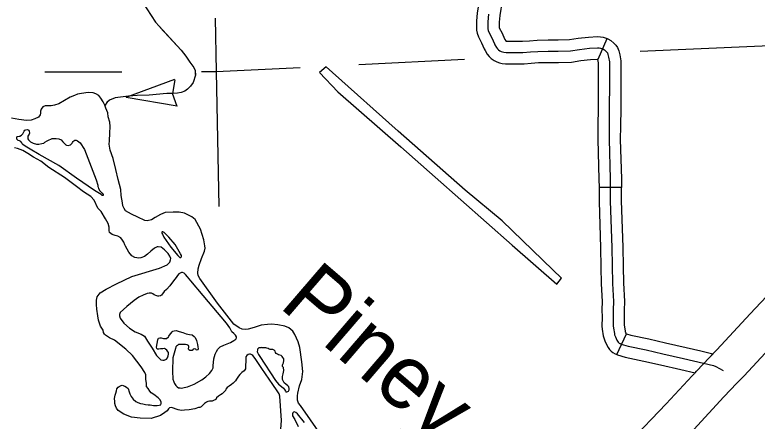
# Model space of a CAD drawing. Extents: x 1084508 to 1142749, y 1057638 to 1093403.
# Drawn here: x 1112809 to 1114355, y 1060030 to 1060877 of the extents above; entities that cross this region are included whole.
import ezdxf

# ---------------------------------------------------------------- set-up
doc = ezdxf.new("R2010")
doc.units = 0
for name, color, linetype in [('Level 15', 7, 'Continuous'), ('Level 31', 7, 'Continuous'), ('Level 35', 7, 'Continuous'), ('Level 43', 7, 'Continuous'), ('Level 45', 7, 'Continuous'), ('Level 5', 7, 'Continuous'), ('Level 57', 7, 'Continuous')]:
    doc.layers.add(name, color=color, linetype=linetype)

msp = doc.modelspace()

# ---------------------------------------------------------------- linework, layer by layer
at = {"layer": 'Level 15'}
for points in [[(1114859, 1060806.8), (1114846.4, 1060793), (1114811.6, 1060755.8), (1114767.8, 1060709.4), (1114736.5, 1060676.9), (1114672.2, 1060608), (1114640.1, 1060572.8), (1114610, 1060541.7), (1114560.6, 1060488.9), (1114524.7, 1060450.4), (1114468.5, 1060391.1), (1114419.6, 1060338.5), (1114340.5, 1060254), (1114270.6, 1060179), (1114255.7, 1060163.4)], [(1114312.6, 1060109.4), (1114327.7, 1060125.1), (1114397.9, 1060200.5), (1114477, 1060285), (1114525.8, 1060337.5), (1114581.8, 1060396.7), (1114617.9, 1060435.3), (1114666.9, 1060487.6), (1114697.3, 1060519.1), (1114729.8, 1060554.8), (1114793.4, 1060622.8), (1114824.6, 1060655.2), (1114868.9, 1060702.1), (1114904, 1060739.7), (1114916.9, 1060753.8)], [(1114255.7, 1060163.4), (1114228.4, 1060134.4), (1114165.6, 1060066.6), (1114088.6, 1059985.7), (1114069.7, 1059965.9), (1114032.8, 1059925.7), (1113985.7, 1059876.6), (1113949.2, 1059837.5), (1113930.3, 1059817.1)], [(1113990.5, 1059766.6), (1114006.7, 1059784.2), (1114042.7, 1059822.7), (1114089.9, 1059872), (1114127, 1059912.3), (1114145.4, 1059931.6), (1114222.8, 1060012.9), (1114285.7, 1060080.8), (1114312.6, 1060109.4)]]:
    msp.add_lwpolyline(points, dxfattribs=at)
at = {"layer": 'Level 31'}
for p, q in [((1114072.5, 1060517.8), (1114025.5, 1060517.8)), ((1114062.8, 1060169.3), (1114082.5, 1060212.5))]:
    msp.add_line(p, q, dxfattribs=at)
for points in [[(1114025.5, 1060517.8), (1114025.5, 1060488.5), (1114028.8, 1060391.8), (1114029.5, 1060351.7)], [(1114049, 1060517.8), (1114049, 1060488.9), (1114052.3, 1060392.4), (1114053.7, 1060317.7), (1114055.8, 1060279.9), (1114055.3, 1060262.2), (1114055.3, 1060247.2), (1114055.3, 1060229.4), (1114055.6, 1060224.6), (1114057.5, 1060213.2), (1114058.1, 1060210.5), (1114059.5, 1060206.2), (1114062.6, 1060199.5), (1114064, 1060197), (1114065.6, 1060194.9), (1114066.4, 1060194.1), (1114067.8, 1060193), (1114069.5, 1060192), (1114071.5, 1060191.2), (1114085.9, 1060186.9), (1114123.7, 1060178.8), (1114158.5, 1060170.6), (1114201.4, 1060161.3), (1114243, 1060151.3), (1114263.6, 1060146.3), (1114268.7, 1060144.5), (1114276.6, 1060140.3), (1114284, 1060136.3)], [(1114076.6, 1060352.5), (1114075.9, 1060393), (1114072.6, 1060489.4), (1114072.5, 1060517.8)], [(1114029.5, 1060351.7), (1114030.1, 1060316.8), (1114032.3, 1060279.6), (1114031.7, 1060262.5), (1114031.8, 1060247.3), (1114031.7, 1060228.6), (1114032.2, 1060221.9), (1114034.4, 1060208.5), (1114035.4, 1060204.1), (1114037.5, 1060197.7), (1114041.7, 1060188.6), (1114044.3, 1060184.1), (1114047.5, 1060179.8), (1114050.6, 1060176.5), (1114054.5, 1060173.5), (1114059.2, 1060170.7), (1114062.8, 1060169.3)], [(1114082.5, 1060212.5), (1114081.5, 1060214.8), (1114080.8, 1060216.8), (1114080.6, 1060217.9), (1114079, 1060227.4), (1114078.8, 1060230.2), (1114078.8, 1060247.2), (1114078.8, 1060261.8), (1114079.4, 1060280.2), (1114077.2, 1060318.6), (1114076.6, 1060352.5)], [(1114082.5, 1060212.5), (1114091.8, 1060209.7), (1114128.9, 1060201.7), (1114163.7, 1060193.5), (1114206.7, 1060184.3), (1114237.8, 1060176.7)], [(1114237.8, 1060176.7), (1114248.5, 1060174.2), (1114262.7, 1060170.7)], [(1114062.8, 1060169.3), (1114064, 1060168.9), (1114080.1, 1060164), (1114118.6, 1060155.8), (1114153.3, 1060147.6), (1114196.2, 1060138.4), (1114225.5, 1060131.3)], [(1114225.5, 1060131.3), (1114228.4, 1060134.4), (1114255.7, 1060163.4), (1114262.7, 1060170.7)]]:
    msp.add_lwpolyline(points, dxfattribs=at)
at = {"layer": 'Level 35'}
for points in [[(1113205.1, 1060396.2), (1113202.6, 1060408.4), (1113195.7, 1060430.6), (1113185, 1060450.7), (1113177.8, 1060456.5), (1113162.4, 1060464), (1113151.3, 1060466.2), (1113138.7, 1060466.2), (1113122.2, 1060465.1), (1113112.5, 1060461.5), (1113101.4, 1060454.7), (1113093.5, 1060450.4), (1113084.9, 1060448.2), (1113080.2, 1060448.6), (1113065.5, 1060455.4), (1113052.2, 1060462.2), (1113040, 1060469), (1113036.8, 1060473.7), (1113034.3, 1060479.1), (1113033.2, 1060485.6), (1113031, 1060500.6), (1113030, 1060513.6), (1113024.6, 1060534), (1113019.6, 1060554.8), (1113014.2, 1060577.8), (1113008.1, 1060595.4), (1113005.9, 1060607.6), (1113006.3, 1060614.8), (1113007, 1060630.6), (1113008.1, 1060644.6), (1113007, 1060653.5), (1113003.8, 1060664.7), (1113002.7, 1060672.9), (1112999.1, 1060683), (1112996.6, 1060689.1), (1112993, 1060695.9), (1112988.7, 1060703.4), (1112984, 1060709.5), (1112977.9, 1060712.8), (1112972.6, 1060714.6), (1112961.8, 1060715.6), (1112948, 1060713.6), (1112939.5, 1060712.1), (1112933.8, 1060709.2), (1112924.5, 1060706), (1112913, 1060698.8), (1112900.8, 1060692), (1112891.6, 1060689), (1112885, 1060688), (1112877.8, 1060688)], [(1112877.8, 1060688), (1112872.8, 1060687.6), (1112867.8, 1060685.5), (1112863.8, 1060680.8), (1112863.1, 1060676.9), (1112863.1, 1060672.6), (1112862, 1060669), (1112858.8, 1060664), (1112850.9, 1060660.4), (1112843, 1060658.2), (1112833.7, 1060657.5), (1112817.9, 1060659.3), (1112802.5, 1060661.8)], [(1113134.1, 1060369.3), (1113131.8, 1060374.6), (1113128.4, 1060380), (1113120.7, 1060387.6), (1113117.3, 1060390.6), (1113113.9, 1060392.9), (1113107.8, 1060393.7), (1113105.9, 1060393.7), (1113099.8, 1060391), (1113092.5, 1060384.5), (1113085.3, 1060378.8), (1113079.2, 1060373.8), (1113071.9, 1060371.2), (1113067.7, 1060370), (1113059.3, 1060371.6), (1113052.9, 1060375.4), (1113046.4, 1060382.6), (1113039.5, 1060395.2), (1113038.4, 1060398.3), (1113036.1, 1060403.2), (1113033.8, 1060407.8), (1113030, 1060412.4), (1113023.5, 1060416.2), (1113018.5, 1060417.7), (1113012, 1060419.6), (1113009, 1060421.5), (1113006.3, 1060423.8), (1113005.9, 1060427.6), (1113005.9, 1060434.9), (1113003.7, 1060442.5), (1112997.9, 1060452.4), (1112989.2, 1060467.3), (1112982.3, 1060474.6), (1112974.3, 1060491), (1112967.4, 1060499), (1112952.2, 1060508.5), (1112937.7, 1060519.6), (1112912.5, 1060538.3), (1112880.1, 1060558.9), (1112863.3, 1060572.6), (1112848, 1060581), (1112836.2, 1060588.3), (1112825.9, 1060594.8), (1112814.9, 1060599), (1112808.4, 1060600.5)], [(1113458.4, 1059985.5), (1113425, 1060032.9), (1113403.9, 1060063.4), (1113399.9, 1060068.1), (1113397.8, 1060074.5), (1113397.8, 1060083.2), (1113398.5, 1060088.5), (1113402.1, 1060104.3), (1113407.1, 1060117.3), (1113409.2, 1060133.8), (1113407.1, 1060153.9), (1113402.8, 1060184), (1113399.5, 1060195.5), (1113392.4, 1060211.3), (1113388.1, 1060218.1), (1113379.8, 1060224.9), (1113371.6, 1060228.5), (1113357.2, 1060231.4), (1113343.6, 1060232.8), (1113335.3, 1060231.8), (1113322.4, 1060230.7), (1113307.3, 1060226), (1113295.1, 1060222.1), (1113289, 1060221.7), (1113282.9, 1060222.1), (1113276.1, 1060224.9), (1113265.4, 1060232.5), (1113231.3, 1060276.6), (1113194.7, 1060327.6), (1113190.7, 1060334.4), (1113190, 1060339.1), (1113191.1, 1060347.7), (1113192.9, 1060355.6), (1113197.9, 1060369.6), (1113204.4, 1060385), (1113205.4, 1060390.8), (1113205.1, 1060396.2)], [(1113055.5, 1060076.2), (1113060.9, 1060071.7), (1113065.4, 1060069), (1113071.2, 1060067.1), (1113075.7, 1060066.3), (1113081.5, 1060065.2), (1113087.2, 1060064.4), (1113091.4, 1060064.4), (1113094.4, 1060063.6), (1113098.2, 1060062.9), (1113101.7, 1060062.9), (1113105.5, 1060062.9), (1113109.7, 1060063.6), (1113113.1, 1060064.8), (1113113.9, 1060067.5), (1113114.3, 1060069.8), (1113112, 1060074.7), (1113107.4, 1060079.3), (1113099, 1060086.2), (1113093.3, 1060089.6), (1113090.6, 1060093), (1113086.8, 1060098.4), (1113083.7, 1060102.9), (1113083.7, 1060108.7), (1113081.8, 1060117.8), (1113081.8, 1060127), (1113080.3, 1060131.6), (1113072.3, 1060143.8), (1113054.4, 1060167), (1113040.7, 1060180.8), (1113016.6, 1060199.5), (1113006.7, 1060204.4), (1112998.3, 1060209.8), (1112996, 1060212.1), (1112994.1, 1060215.1), (1112993, 1060220.1), (1112988, 1060228.5), (1112983.4, 1060241.1), (1112981.9, 1060249.8), (1112980, 1060264), (1112979.2, 1060273.5), (1112979.2, 1060282.7), (1112980.8, 1060289.5), (1112987.3, 1060297.9), (1112999.5, 1060305.5), (1113020.8, 1060317), (1113053.2, 1060332.3), (1113110.4, 1060349.4), (1113126.8, 1060356.3), (1113132.2, 1060361.6), (1113133.7, 1060366.6), (1113134.1, 1060369.3)], [(1113250, 1060234.4), (1113201.2, 1060292.1), (1113175.4, 1060323), (1113168.6, 1060331.6), (1113164.7, 1060335.9), (1113161.8, 1060338.8), (1113158.6, 1060340.2), (1113156.4, 1060340.2), (1113154.6, 1060339.9), (1113151, 1060337.7), (1113148.2, 1060334.1), (1113144.9, 1060330.2), (1113139.6, 1060322.6), (1113132, 1060312.2), (1113124.9, 1060305.1), (1113120.5, 1060300.4), (1113117, 1060296.1), (1113114.4, 1060293.2), (1113112.3, 1060291.4), (1113109.1, 1060290.7), (1113106.9, 1060290.7), (1113102.6, 1060292.1), (1113099.4, 1060293.9), (1113096.5, 1060295.7), (1113094, 1060297.2), (1113089, 1060297.2), (1113085, 1060296.4), (1113076.8, 1060292.9), (1113067.5, 1060288.9), (1113058.1, 1060281.7), (1113042.7, 1060269.2), (1113028.7, 1060256.6), (1113026.9, 1060252.7), (1113026.9, 1060249.8), (1113028.4, 1060244.8), (1113036.3, 1060234.4), (1113047.7, 1060224), (1113059.9, 1060216.4), (1113072.5, 1060211.8), (1113079.3, 1060207.3), (1113085.3, 1060197.2), (1113095.5, 1060182.4), (1113104.5, 1060167.3), (1113110, 1060161.5), (1113113.5, 1060158.5), (1113117.6, 1060157.4), (1113120.4, 1060157.4), (1113124.8, 1060159.4), (1113127.5, 1060162.1), (1113128.3, 1060166.5)], [(1113171.1, 1060182.4), (1113171.9, 1060184.3), (1113171.9, 1060185.9), (1113170.8, 1060188.1), (1113168, 1060189.8), (1113164.5, 1060190), (1113159, 1060190), (1113155.7, 1060190), (1113153, 1060190), (1113150.2, 1060190), (1113147.8, 1060188.4), (1113146.1, 1060187), (1113144.8, 1060185.1), (1113143.7, 1060182.1), (1113138.5, 1060162.4), (1113137.6, 1060134.7), (1113138.5, 1060118.3), (1113140.1, 1060112.5), (1113141.5, 1060108.9), (1113144.2, 1060104.6), (1113147.2, 1060101.8), (1113150.2, 1060100.2), (1113153.8, 1060099.6), (1113156, 1060099.3), (1113162, 1060100.7), (1113168.6, 1060101.8), (1113182.6, 1060107.8), (1113198.4, 1060116.3), (1113207.2, 1060122.6), (1113214.9, 1060130), (1113219.5, 1060136.3), (1113222.3, 1060141.8), (1113222.5, 1060146.2), (1113222.8, 1060152.5), (1113223.4, 1060160.7), (1113226.1, 1060170), (1113229.1, 1060175.8), (1113231.6, 1060180.5), (1113237.1, 1060185.4), (1113244.5, 1060188.7), (1113258.1, 1060194.4), (1113265, 1060198.8), (1113269.7, 1060201.6), (1113270.7, 1060204.3), (1113270.7, 1060205.9), (1113268.6, 1060210), (1113265.3, 1060213.1), (1113260.9, 1060216.9), (1113256.8, 1060225.1), (1113250, 1060234.4)], [(1113128.3, 1060166.5), (1113129.2, 1060169.8), (1113129.2, 1060173.9), (1113127.5, 1060176.3), (1113126.1, 1060178.5), (1113123.1, 1060180.5), (1113120.7, 1060181.8), (1113117.4, 1060181.5), (1113112.7, 1060181), (1113108.9, 1060180.5), (1113105.9, 1060180.7), (1113104.8, 1060182.1), (1113104.2, 1060184.6), (1113105.3, 1060192.5), (1113107, 1060199.9), (1113108.3, 1060203.2), (1113111.3, 1060204.3), (1113113.8, 1060204.3), (1113118.5, 1060202.6), (1113122.6, 1060202.9), (1113125, 1060202.9), (1113128.9, 1060206.2), (1113130.2, 1060207.9), (1113131.6, 1060209.5), (1113134.4, 1060213.3), (1113136.8, 1060216.3), (1113138.2, 1060217.7), (1113140.9, 1060218.8), (1113145.3, 1060219.1), (1113151.6, 1060217.2), (1113159, 1060215), (1113166.1, 1060212.5), (1113173.2, 1060211.4), (1113178.4, 1060210.6), (1113182.8, 1060207), (1113184.7, 1060204.8), (1113187.2, 1060198.5), (1113189.7, 1060190), (1113190.5, 1060185.1), (1113191.3, 1060181), (1113190.2, 1060178.8), (1113189.1, 1060178.3), (1113186.9, 1060179.1), (1113185.8, 1060180.5), (1113183.7, 1060181), (1113180.9, 1060180.5), (1113178.2, 1060177.7), (1113176.3, 1060177.7), (1113173.5, 1060177.7), (1113171.9, 1060178.8), (1113170.8, 1060180.2), (1113171.1, 1060182.4)], [(1113362.5, 1060004.5), (1113364.5, 1060032), (1113361, 1060082.7), (1113359.9, 1060087.7), (1113355.3, 1060093.4), (1113346.5, 1060106.8), (1113323.6, 1060140.3), (1113309.9, 1060160.9), (1113304.6, 1060167.4), (1113302.7, 1060169), (1113300, 1060170.1), (1113297.7, 1060170.1), (1113295, 1060169.7), (1113292.4, 1060167.4), (1113290.5, 1060164.8), (1113290.1, 1060160.6), (1113290.1, 1060155.2), (1113289.7, 1060146.4), (1113289.7, 1060142.6), (1113289.3, 1060139.2), (1113286.6, 1060135.4), (1113282.1, 1060131.6), (1113277.9, 1060127.7), (1113274.8, 1060124.3), (1113271, 1060118.2), (1113268.7, 1060114.8), (1113267.6, 1060113.2), (1113264.1, 1060109.8), (1113260.7, 1060106.8), (1113255.8, 1060103.7), (1113251.6, 1060100.7), (1113248.9, 1060096.8), (1113247.7, 1060094.2), (1113243.2, 1060089.2), (1113241.3, 1060087.7), (1113237.8, 1060085.4), (1113233.6, 1060082.7)], [(1113233.6, 1060082.7), (1113229.4, 1060078.9), (1113227.5, 1060075.9), (1113223, 1060073.2), (1113220.3, 1060072.4), (1113217.6, 1060072.4), (1113214.9, 1060072.4), (1113211.1, 1060071.3), (1113208.1, 1060069.8), (1113203.9, 1060067.5), (1113201.2, 1060064.4), (1113197, 1060060.6), (1113194.4, 1060059.1), (1113191.7, 1060059.1), (1113184.4, 1060056.4), (1113172.6, 1060053.7), (1113162.3, 1060053.3), (1113156.2, 1060052.6), (1113149.7, 1060053.7), (1113135.2, 1060058.7), (1113131.4, 1060057.9), (1113129.5, 1060056.4), (1113126.5, 1060052.2), (1113121.5, 1060048.4), (1113112.7, 1060042.3), (1113092.9, 1060036.2), (1113070.4, 1060036.6), (1113052.1, 1060038.5), (1113036.1, 1060045.3), (1113024.6, 1060052.6), (1113021.2, 1060057.5), (1113018.9, 1060062.1), (1113017.4, 1060067.5), (1113017.4, 1060071.7), (1113017, 1060077.8), (1113018.5, 1060084.6), (1113019.7, 1060088.8), (1113020.8, 1060093.8), (1113022, 1060097.6), (1113024.6, 1060101), (1113026.2, 1060102.6), (1113030.7, 1060104.9), (1113033, 1060105.2), (1113038.4, 1060103.3), (1113041.8, 1060101.4), (1113045.2, 1060098.4), (1113047.5, 1060091.9), (1113049, 1060087.3), (1113051.3, 1060081.6), (1113055.5, 1060076.2)], [(1113412.1, 1060027.3), (1113398.1, 1060045.7), (1113394, 1060048.8), (1113391.2, 1060049.7), (1113389.4, 1060049.4), (1113387.8, 1060047.9), (1113387.5, 1060045.4), (1113387.5, 1060041.6), (1113392.5, 1060033.8), (1113399.3, 1060019.2)]]:
    msp.add_lwpolyline(points, dxfattribs=at)
for points in [[(1112975.3, 1060511.1), (1112937.4, 1060536.9), (1112900.6, 1060563.2), (1112860.3, 1060586.6), (1112841.1, 1060597.7), (1112830.8, 1060603.5), (1112826.1, 1060607.2), (1112824.7, 1060608.8), (1112823.7, 1060610.3), (1112821.6, 1060613.5), (1112819, 1060614.8), (1112816.3, 1060615.6), (1112815.3, 1060616.4), (1112813.4, 1060618.2), (1112813.2, 1060619.3), (1112813.2, 1060620.9), (1112813.4, 1060623), (1112814.7, 1060624), (1112818.4, 1060624.3), (1112819.7, 1060624.6), (1112823.4, 1060626.4), (1112826.3, 1060629.3), (1112828.7, 1060634.8), (1112830.3, 1060636.7), (1112831.9, 1060638), (1112834.8, 1060638.5), (1112836.9, 1060638), (1112838.2, 1060636.9), (1112839.5, 1060635.1), (1112840, 1060630.6), (1112839.2, 1060629), (1112836.6, 1060624.3), (1112836.1, 1060621.4), (1112836.3, 1060619), (1112837.6, 1060616.7), (1112841.9, 1060612.7), (1112847.4, 1060609.8), (1112854.5, 1060608), (1112859.2, 1060608), (1112865.6, 1060609), (1112869.5, 1060610.1), (1112871.6, 1060612.2), (1112876.3, 1060614.8), (1112880.6, 1060617.2), (1112884, 1060618.2), (1112887.1, 1060619.3), (1112890.6, 1060619.3), (1112895.3, 1060619.8), (1112900.8, 1060619), (1112905.6, 1060616.9), (1112909.5, 1060613), (1112914, 1060608), (1112915.6, 1060606.1), (1112917.1, 1060605.6), (1112920.6, 1060605.3), (1112925, 1060606.1), (1112927.2, 1060608.2), (1112928.7, 1060610.1), (1112929.5, 1060611.4), (1112930.8, 1060613.2), (1112931.9, 1060614.8), (1112934.5, 1060616.4), (1112937.2, 1060616.4), (1112940.1, 1060614.8), (1112945.1, 1060610.6), (1112954.5, 1060596.6), (1112978.7, 1060533.4), (1112982.2, 1060522.1), (1112982.4, 1060519.5), (1112982.7, 1060518.2), (1112983.5, 1060515.5), (1112986.6, 1060510.3), (1112991.1, 1060505.8), (1112993.5, 1060502.6), (1112993.5, 1060501.8), (1112993.5, 1060501), (1112992.2, 1060500.5), (1112991.1, 1060500.5), (1112988.8, 1060502.9)], [(1113154.2, 1060379.3), (1113143.4, 1060398.6), (1113130.2, 1060414), (1113124.2, 1060419.8), (1113119.9, 1060423.5), (1113117.1, 1060425.4), (1113115.8, 1060425.4), (1113115.2, 1060424.4), (1113115.6, 1060422.1), (1113116.5, 1060420.1), (1113119.7, 1060414), (1113134, 1060393.2), (1113148.4, 1060375.8), (1113151.9, 1060372.5), (1113152.9, 1060371.7), (1113154, 1060371.6), (1113154.8, 1060371.7), (1113155.3, 1060372.4), (1113156.1, 1060373.4), (1113156.1, 1060374.3), (1113156.1, 1060375.7)], [(1113319.7, 1060165), (1113352.1, 1060115.2), (1113358.2, 1060107.7), (1113364.4, 1060102.7), (1113368.4, 1060099.1), (1113371, 1060096.3), (1113372.9, 1060093), (1113373.7, 1060091.8), (1113375.6, 1060091.6), (1113377.9, 1060092), (1113379.1, 1060093), (1113380.5, 1060095.6), (1113380.5, 1060098.4), (1113380, 1060102), (1113377.7, 1060104.1), (1113373.7, 1060107.4), (1113370.3, 1060110.3), (1113368.4, 1060112.9), (1113366.8, 1060117.6), (1113366.8, 1060123.5), (1113367.9, 1060129.2), (1113369.1, 1060136.3), (1113368.4, 1060142.2), (1113366.6, 1060144.6), (1113366.5, 1060145.8), (1113366.5, 1060147), (1113367.5, 1060149.3), (1113368.9, 1060152.2), (1113369.2, 1060156.7), (1113369.1, 1060160.2), (1113367.5, 1060163.1), (1113365.6, 1060165.4), (1113363.5, 1060167.1), (1113361.3, 1060168.2), (1113358.3, 1060169), (1113356.4, 1060169.9), (1113353.7, 1060171.3), (1113352.1, 1060173.5), (1113351.1, 1060176.3), (1113349.2, 1060178.2), (1113346.2, 1060179.8), (1113344.1, 1060179.8), (1113340.7, 1060179.8), (1113338.6, 1060180.5), (1113336.7, 1060181.8), (1113334.3, 1060182.7), (1113331.9, 1060183.2), (1113329.3, 1060183.2), (1113327.4, 1060183.2), (1113326.1, 1060183.2), (1113324.1, 1060183.6), (1113322.9, 1060183.7), (1113321.7, 1060183.6), (1113319.6, 1060183.6), (1113317.5, 1060183.1), (1113315.9, 1060181.8), (1113314.7, 1060180.6), (1113314.2, 1060178.2), (1113314, 1060175.8), (1113314.6, 1060173.4), (1113316.5, 1060169.4)]]:
    msp.add_lwpolyline(points, close=True, dxfattribs=at)
at = {"layer": 'Level 43'}
for p, q in [((1113041.1, 1060705.9), (1113142.2, 1060743)), ((1113142.6, 1060741.9), (1113137.4, 1060713.7)), ((1113041.1, 1060705.9), (1113147.3, 1060687.5)), ((1113147, 1060686.3), (1113137.4, 1060713.3))]:
    msp.add_line(p, q, dxfattribs=at)
for points in [[(1113047.8, 1060945.9), (1113102.1, 1060861.9), (1113155.3, 1060804.1), (1113165.6, 1060791.3), (1113173.5, 1060778.9), (1113181.7, 1060767.7), (1113184.6, 1060761.1), (1113185.1, 1060752), (1113180.9, 1060736.7), (1113175.1, 1060728.4), (1113168.5, 1060722.2), (1113163.1, 1060718.1), (1113155.7, 1060715.6), (1113147.8, 1060714.4), (1113137.5, 1060713.5), (1113125.5, 1060713.5), (1113089.1, 1060710.2), (1113063.9, 1060709), (1113046.2, 1060707.7), (1113034.6, 1060706.5), (1113018.5, 1060704.4), (1113006.5, 1060699.5), (1113001.1, 1060694.5), (1112997.7, 1060689.3)], [(1113112, 1060851.2), (1113155.3, 1060804.1), (1113165.6, 1060791.3), (1113173.5, 1060778.9), (1113181.7, 1060767.7), (1113184.6, 1060761.1), (1113185, 1060753)], [(1113164.2, 1060718.9), (1113163.1, 1060718.1), (1113155.7, 1060715.6), (1113147.8, 1060714.4), (1113137.5, 1060713.5), (1113125.5, 1060713.5), (1113089.1, 1060710.2), (1113063.9, 1060709), (1113046.2, 1060707.7), (1113041, 1060707.2)], [(1113002.3, 1060695.6), (1113001.1, 1060694.5), (1112997.7, 1060689.3)]]:
    msp.add_lwpolyline(points, dxfattribs=at)
at = {"layer": 'Level 45'}
msp.add_line((1114023.7, 1060784.8), (1114042.6, 1060827.9), dxfattribs=at)
for points in [[(1113777.5, 1060914.8), (1113771.9, 1060881.4), (1113770.7, 1060864.1), (1113770.4, 1060850.2), (1113770.6, 1060845.6), (1113771.8, 1060839), (1113774.3, 1060831.5), (1113781.2, 1060819.1), (1113786.3, 1060806.6), (1113788.4, 1060803), (1113792.6, 1060795.7), (1113796.8, 1060790.7), (1113801.3, 1060786.3), (1113807.3, 1060782.2), (1113813.1, 1060779.3), (1113818.4, 1060777.5), (1113823.6, 1060776.3), (1113830.8, 1060775.5), (1113846.8, 1060775.1), (1113867.5, 1060775.3), (1113869.9, 1060775.4)], [(1113823.9, 1060906.9), (1113818.7, 1060875.9), (1113817.7, 1060862.1), (1113817.5, 1060850.8), (1113817.5, 1060850.7), (1113817.6, 1060850.6), (1113817.6, 1060850.5), (1113823.7, 1060839.5), (1113828.8, 1060827.1), (1113829.3, 1060826.2), (1113831.2, 1060822.9), (1113831.2, 1060822.9), (1113831.4, 1060822.8), (1113831.6, 1060822.8), (1113833.7, 1060822.6), (1113847.2, 1060822.2), (1113865.6, 1060822.3), (1113866.5, 1060822.4)], [(1113795.3, 1060878.7), (1113794.2, 1060863.1), (1113794, 1060850.5), (1113794.1, 1060848.2), (1113794.7, 1060844.8), (1113795.9, 1060841), (1113802.5, 1060829.3), (1113807.6, 1060816.8), (1113808.8, 1060814.6), (1113811.9, 1060809.2), (1113813.9, 1060806.8), (1113816.3, 1060804.6), (1113819.3, 1060802.5), (1113822.1, 1060801.1), (1113824.9, 1060800.2), (1113827.6, 1060799.5), (1113832.3, 1060799), (1113847, 1060798.7), (1113866.6, 1060798.8), (1113882.6, 1060800), (1113898.1, 1060801.3), (1113919.8, 1060801.9), (1113940.8, 1060801.9), (1113966.4, 1060802.6), (1113984.8, 1060805.4), (1114005.7, 1060807.6), (1114022.7, 1060808.6), (1114025.8, 1060808.4), (1114028.9, 1060807.8), (1114031, 1060807.3), (1114033.4, 1060806.2), (1114036.8, 1060804.2), (1114040, 1060801.7), (1114041.7, 1060799.7), (1114042.9, 1060797.9), (1114044.2, 1060794.8), (1114045.6, 1060789), (1114047.1, 1060779.6), (1114047.1, 1060733.7), (1114047, 1060682.6), (1114046.4, 1060617.5), (1114049, 1060535.5), (1114049, 1060517.8)], [(1113866.5, 1060822.4), (1113880.7, 1060823.4), (1113896.7, 1060824.8), (1113919.5, 1060825.4), (1113940.5, 1060825.4), (1113964.2, 1060826.1), (1113981.8, 1060828.8), (1114003.8, 1060831.1), (1114022.6, 1060832.2), (1114028.7, 1060831.9), (1114034.1, 1060830.8), (1114038.6, 1060829.7), (1114042.6, 1060827.9)], [(1114042.6, 1060827.9), (1114044.1, 1060827.2), (1114050.2, 1060823.7), (1114056.5, 1060818.7), (1114060.5, 1060813.9), (1114063.8, 1060809), (1114066.6, 1060802.2), (1114068.7, 1060793.8), (1114070.6, 1060781.4), (1114070.7, 1060733.7), (1114070.6, 1060682.5), (1114070.2, 1060645.6)], [(1113869.9, 1060775.4), (1113884.4, 1060776.5), (1113899.4, 1060777.8), (1113920.1, 1060778.3), (1113941.2, 1060778.3), (1113968.5, 1060779.1), (1113987.8, 1060782.1), (1114007.6, 1060784.1), (1114022.8, 1060785), (1114022.8, 1060785), (1114023.4, 1060784.9), (1114023.7, 1060784.8)], [(1114022.3, 1060785.4), (1114022.5, 1060784.3), (1114023.6, 1060777.7), (1114023.6, 1060733.7), (1114023.5, 1060682.8), (1114023.1, 1060646.1)], [(1114023.1, 1060646.1), (1114022.8, 1060617.3), (1114025.4, 1060535.1), (1114025.5, 1060517.8)], [(1114070.2, 1060645.6), (1114069.9, 1060617.8), (1114072.5, 1060535.9), (1114072.5, 1060517.8)]]:
    msp.add_lwpolyline(points, dxfattribs=at)
at = {"layer": 'Level 5'}
for points in [[(1113226.6, 1060870.4), (1113228.6, 1060759.2)], [(1114110.9, 1060801.5), (1114603.2, 1060823.2)], [(1113525.5, 1060774), (1113745.6, 1060784.9)], [(1113228.6, 1060759.2), (1113403.2, 1060767.9)], [(1112872, 1060758.3), (1113032.2, 1060758.7)], [(1113198.2, 1060759.1), (1113228.6, 1060759.2)], [(1113228.6, 1060759.2), (1113234.3, 1060477.7)]]:
    msp.add_lwpolyline(points, dxfattribs=at)
at = {"layer": 'Level 57'}
for p, q in [((1113457.3, 1060769.1), (1113443.7, 1060756.9)), ((1113470.4, 1060756.9), (1113457.3, 1060769.1)), ((1113443.7, 1060756.9), (1113481.8, 1060717)), ((1113607.6, 1060634.6), (1113470.4, 1060756.9)), ((1113481.8, 1060717), (1113612.9, 1060602.1)), ((1113746.9, 1060511.8), (1113607.6, 1060634.6)), ((1113612.9, 1060602.1), (1113684.3, 1060539)), ((1113684.3, 1060539), (1113844.6, 1060397)), ((1113823.6, 1060447.8), (1113746.9, 1060511.8)), ((1113929.2, 1060345.7), (1113823.6, 1060447.8)), ((1113844.6, 1060397), (1113938, 1060316.3)), ((1113947.2, 1060328.2), (1113929.2, 1060345.7)), ((1113938, 1060316.3), (1113947.2, 1060328.2))]:
    msp.add_line(p, q, dxfattribs=at)

# ---------------------------------------------------------------- texts
at = {"layer": 'Level 35'}
msp.add_text('Piney', height=132.58, rotation=319.3355, dxfattribs=at).set_placement((1113356.7, 1060269.8))

doc.saveas('drawing.dxf')
